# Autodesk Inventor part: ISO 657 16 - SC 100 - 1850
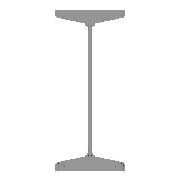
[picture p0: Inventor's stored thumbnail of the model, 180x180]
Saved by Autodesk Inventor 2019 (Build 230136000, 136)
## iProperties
_CCFamilyMember: 1
_CCFamilyDisplayName: ISO 657/16 - 1980 - Poutres en acier laminées à chaud - Partie 16: profilés en H (série métrique) - Cotes et propriétés de section
_FrameMemberDoc: Frame Member File
_Version: 15.0.0
_GetPNFromCC: 1
Created: 2018-07
Part Number: ISO 657 16 - SC 100 - 1850
Material: Acier, doux
Description: Poutres en acier laminées à chaud - Partie 16: profilés en H (série métrique) - Cotes et propriétés de section
Document SubType Name: Modeling
Standard: ISO
Designer: Fabian Perrée
Standard Revision: First edition 1980-02-15
Standards Organization: ISO
Language: fr-FR
Size Designation: SC 100
Categories: <MemberInstance><Categories><Category DisplayName="Profilés" InternalName="089c4875-fa83-4c05-b084-43b9cc11f5ed" Mnemonic="GRDR"><CategoryParameter DisplayName=
Stock Number: SC 100
Density: 7.85 g/cm^3
Appearance: Semi-poli
Mass: 36980.1 g
Surface Area: 10064.8 cm^2
Volume: 4710.84 cm^3
IsCustomPart: 1
G_W: 100,000 mm
G_H: 100,000 mm
G_L: 1850,000 mm
+3996474A-F15E-4C0C-B350-EF0BE35A7832+DETAILDECOUPE6: Angle de coupe 90,00 deg
+49FB2D49-B789-45CC-8DEB-3E9423125D72+DETAILDECOUPE7: Angle de coupe 90,00 deg
Author: Fabian Perrée
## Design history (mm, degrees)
node "Plan de départ"
node "Plan de fin"
sketch "Esquisse"
  geometry: L1 (-3, 0)-(-3, -26.266); L2 (-13.33, -38.149)-(-44.835, -42.577); L3 (-50, -48.518)-(-50, -50); L4 (-50, -50)-(0, -50); L5 (-26.5, -50)-(-26.5, -40); L6 (-61.333, 0)-(81.777, 0); L7 (0, 0)-(0, -50); L8 (0, -60)-(0, 80); L9 (3, 0)-(3, -26.266); L10 (13.33, -38.149)-(44.835, -42.577); L11 (50, -48.518)-(50, -50); L12 (50, -50)-(0, -50); L13 (-3, 0)-(0, 0); L14 (-3, 0)-(-3, 26.266); L15 (-13.33, 38.149)-(-44.835, 42.577); L16 (-50, 48.518)-(-50, 50); L17 (-50, 50)-(0, 50); L18 (50, 48.518)-(50, 50); L19 (13.33, 38.149)-(44.835, 42.577); L20 (3, 0)-(3, 26.266); L21 (50, 50)-(0, 50); L22 (0, 108)-(0, -88) reference; L23 (-89.955, 0)-(110.399, 0) reference; A1 r 6 centre (-44, 48.518) between (-50, 48.518) and (-44.835, 42.577); A2 r 6 centre (44, 48.518) between (44.835, 42.577) and (50, 48.518); A3 r 6 centre (44, -48.518) between (50, -48.518) and (44.835, -42.577); A4 r 6 centre (-44, -48.518) between (-44.835, -42.577) and (-50, -48.518); A5 r 12 centre (-15, 26.266) between (-3, 26.266) and (-13.33, 38.149); A6 r 12 centre (15, 26.266) between (13.33, 38.149) and (3, 26.266); A7 r 12 centre (15, -26.266) between (3, -26.266) and (13.33, -38.149); A8 r 12 centre (-15, -26.266) between (-13.33, -38.149) and (-3, -26.266); 14 further points
  constraints: 42 end point, 24 point on line, 17 symmetric about line, 16 point on circle, 16 tangent, 8 centre point, 6 equal radius, 4 collinear, 2 perpendicular, 12 other
  dimensions: "d1" = 10 vertical distance of L3.end L5.end (= G_T1); "d2" = 23.5 distance between parallel lines of L5 L3 (= -0.25 x G_T + 0.25 x G_W); "d3" = 3 distance between parallel lines of L1 L7 (= 0.5 x G_T); "d4" = 50 distance between parallel lines of L7 L3 (= 0.5 x G_W); "d9" = 50 distance from line of L1.start L4 (= 0.5 x G_H); "d14" = 98 deg angle of L2 L1 (= G_NG); "d15" = 6 radius of A1 (= G_ER); "d16" = 12 radius of A5 (= G_IR)
extrude "Corps" new body sketch "Esquisse" stored distance "d5" = 1850 (= G_L); taper "d6" = 0 deg
node "Driven Length"
  sketch "Sketch3"
    geometry: L1 (0, 0)-(10, 0) reference
    constraints: 2 end point, 1 horizontal
  workplane "Work Plane3"
  sketch "Sketch4"
    geometry: L1 (-2, -50)-(12, -50) reference; L2 (-2, 1800)-(12, 1800) reference
    dimensions: "d20" = 1850 distance between parallel lines of L1 L2 (derived)
node "Plan de construction17"
feature "Scission5"
node "Plan de construction18"
feature "Scission6"
body "Solid1"
other parameters: "G_W" = 100 (= G_H) [user parameter; used in 2 equation terms], "G_H" = 100 [user parameter; used in 2 equation terms], "G_T" = 6 [user parameter; used in 2 equation terms], "G_T1" = 10 [user parameter; used in 1 equation term], "G_L" = 1850 (= d20) [user parameter; used in 1 equation term], "G_ER" = 6 [user parameter; used in 1 equation term], "G_IR" = 12 [user parameter; used in 1 equation term], "G_NG" = 98 deg [user parameter; used in 1 equation term], "d19" = 90 deg
